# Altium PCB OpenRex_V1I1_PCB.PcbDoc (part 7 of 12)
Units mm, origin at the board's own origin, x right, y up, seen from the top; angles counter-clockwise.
Board outline 70 x 95 mm, 10 copper layers (L1, L2, L3, L4 (PWR), L5 (PWR), L6 (PWR), L7 (PWR), L8, L9, L10), stack 1.632 mm thick; 1080 components, 708 nets, 3831 pads, 2373 vias.
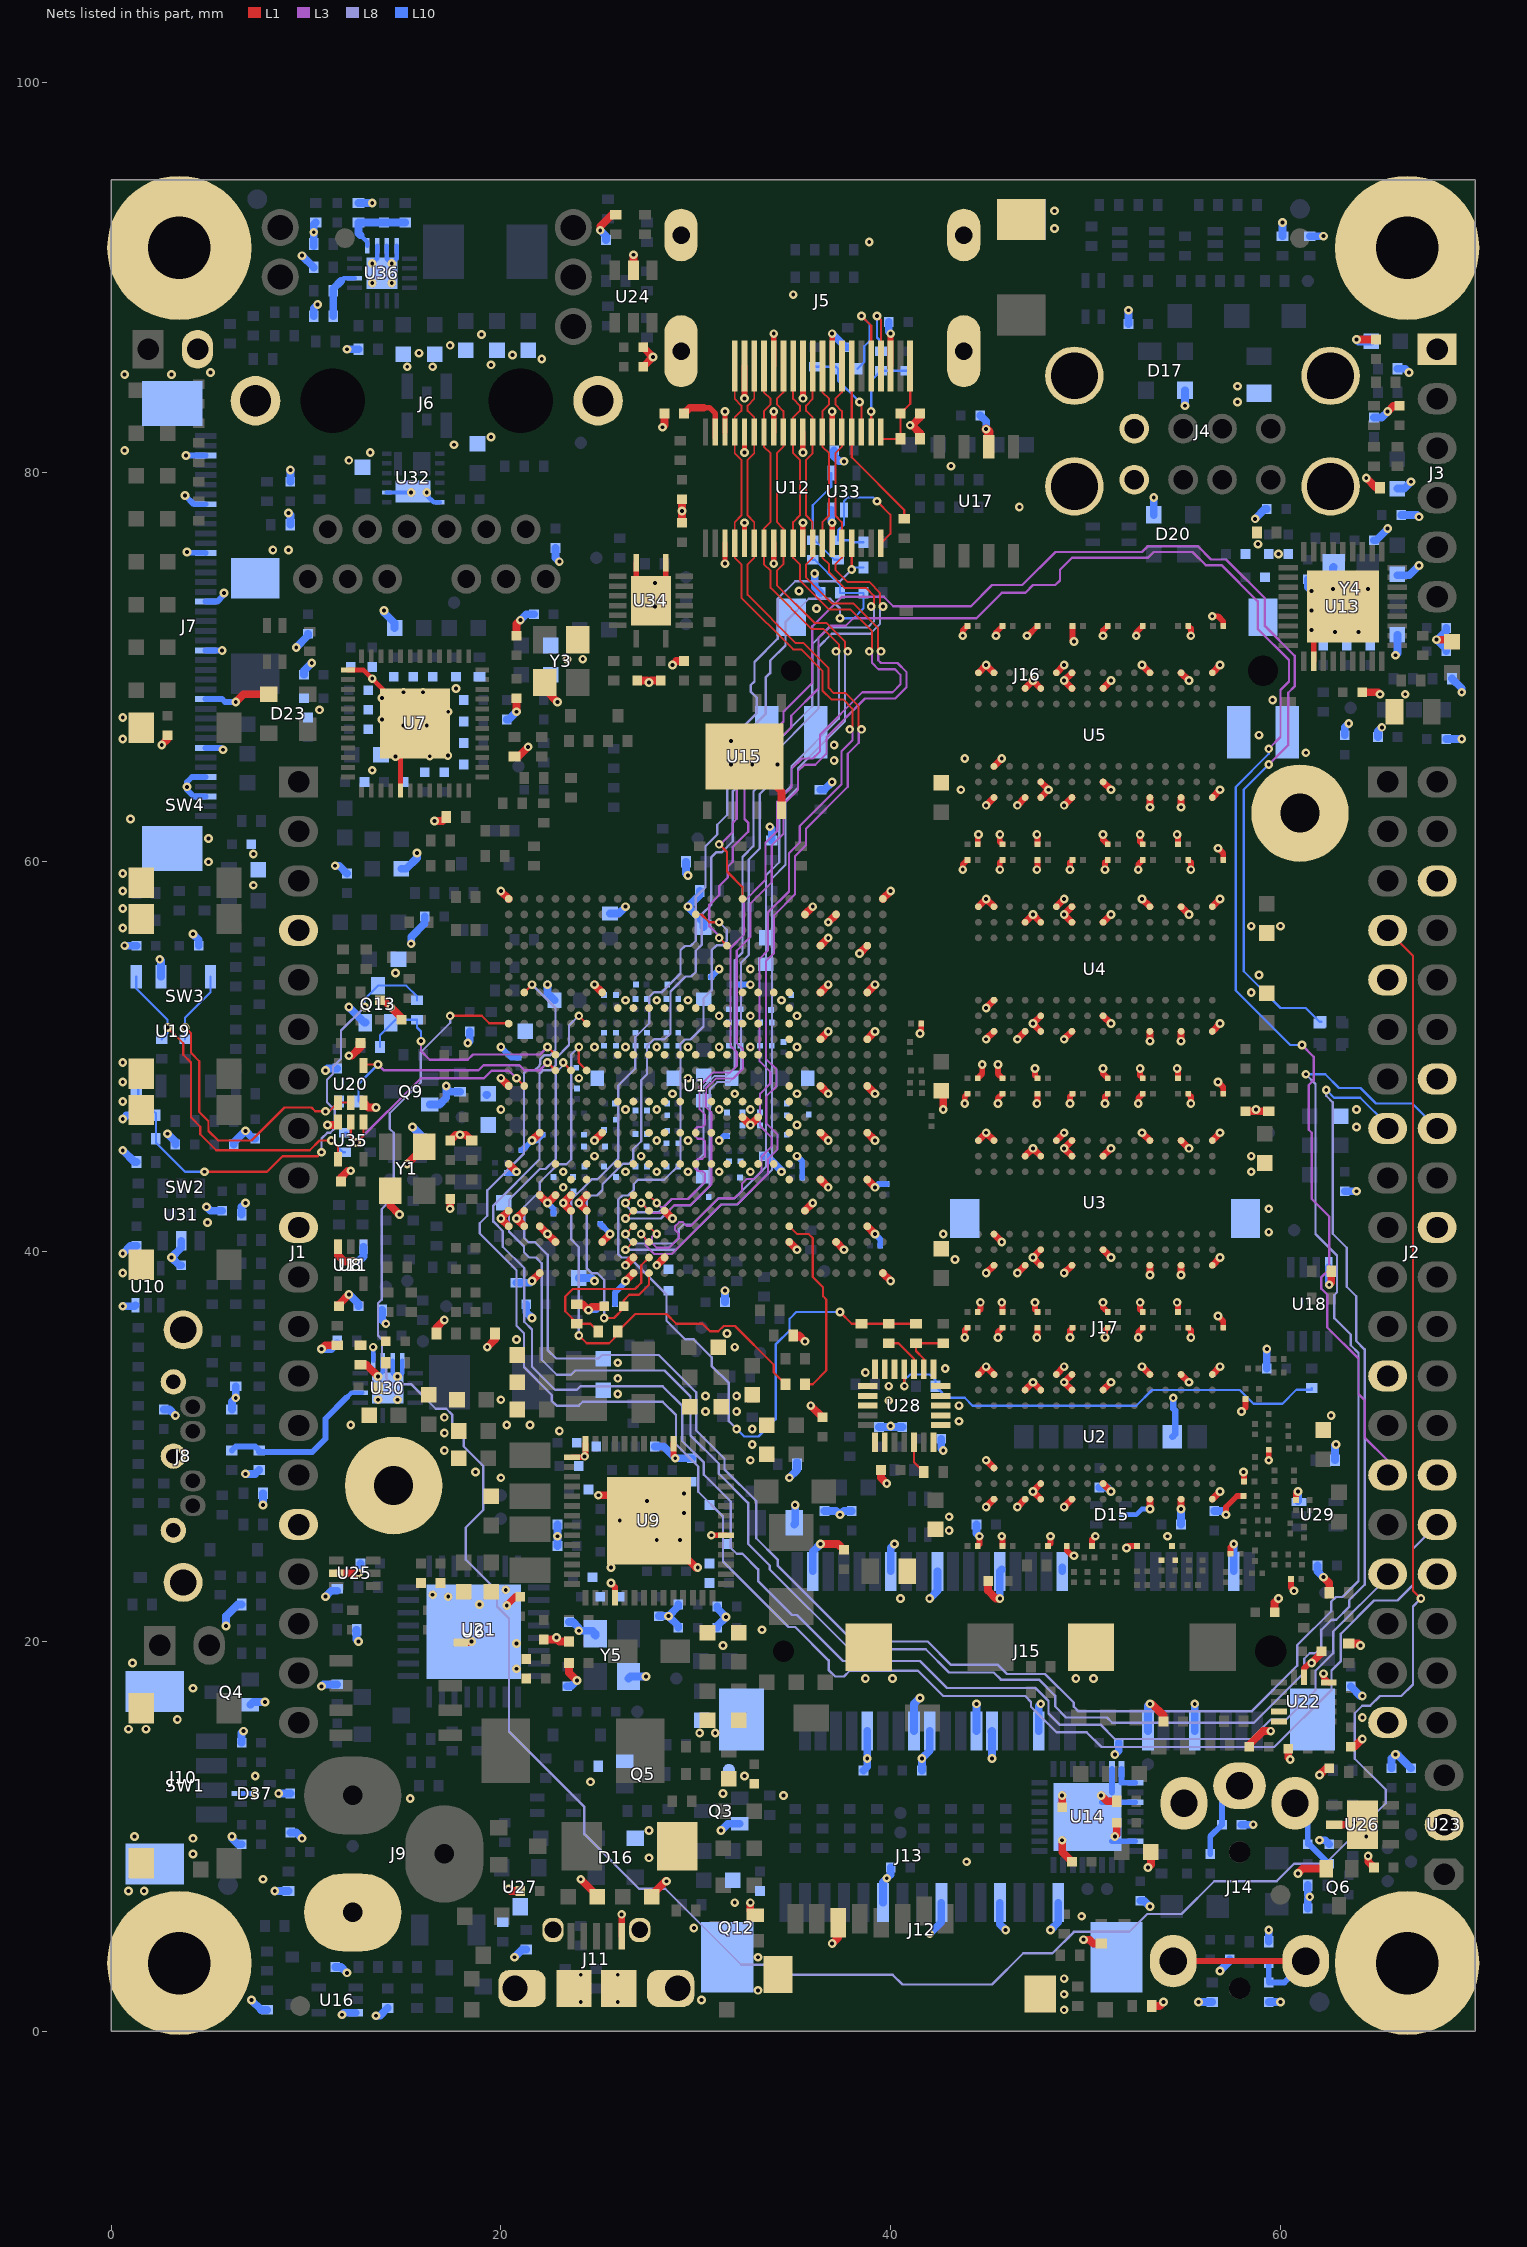
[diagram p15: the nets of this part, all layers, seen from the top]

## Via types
v1: diameter 0.45, hole 0.2, L1 to L10, tented both sides, 2369 vias
v2: diameter 1, hole 0.5, L1 to L10, tented top, 4 vias

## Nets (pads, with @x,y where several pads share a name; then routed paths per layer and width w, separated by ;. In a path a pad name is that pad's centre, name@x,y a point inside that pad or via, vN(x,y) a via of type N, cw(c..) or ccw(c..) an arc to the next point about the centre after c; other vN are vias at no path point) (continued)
FB_1V375: C410.1 R336.1 R339.2 U30.9 | length 0.7
  L10 w0.23: U30.9@13.45,34.4 U30.9@13.45,34.41 v1(13.45,35.1)
FB_3V3_HDR: C432.1 R399.1 R402.2 U36.9 | length 3.8
  L10 w0.23: 12.8,92.15 13.15,91.8 U36.9@13.15,91.61
  L10 w0.4: 12.8,92.15 12.7,92.25 R402.2@12.7,92.8 C432.1@14,92.8 R399.1@15.1,92.8
FIL_HP_OUTL: C287.1 FB22.2 J14.3 J14.4 | length 10.3
  L1 w0.3: J14.3@54.5,3.6 J14.4@61.3,3.6
  L10 w0.3: FB22.2@59.4,3.6 FB22.2@59.4,3.5 C287.1@59.4,2.5 60.2,2.5 J14.4@61.3,3.6
FIL_HP_OUTR: C286.1 FB21.2 J14.2 | length 3.9
  L10 w0.3: J14.2@60.75,11.7 61.4,11.05 FB21.2@61.4,9.6 61.479,9.6 62.479,8.6 C286.1@62.5,8.6
FIL_MIC_IN: C295.1 FB18.2 J14.1 | length 4.1
  L10 w0.3: FB18.2@56.4,9.1 56.4,10 C295.1@57,10.6 57,11.7 J14.1@57.9,12.6
FLEXCAN1_RX: R412.1 U1.D14 U20.4 | length 12.8
  L1 w0.114: U20.4@12.95,49.55 13,49.6 v1(13.7,49.6) ; v1(22.4,49.7) U1.D14@22.8,49.3
  L3 w0.12: v1(13.7,49.6) 14,49.3 18.845,49.3 19.11,49.565 20.95,49.565 21.2,49.315 22.015,49.315 v1(22.4,49.7)
  L10 w0.114: R412.1@12.7,47.7 12.7,48.6 v1(13.7,49.6)
FLEXCAN1_RX_BUFF: R117.1 R412.2 U19.4 U20.1 U20.2 | length 18.9
  L1 w0.114: v1(3.8,51.5) 4.1,51.2 4.1,50.2 4.53,49.77 4.53,47.17 5.004,46.696 5.004,46.196 5.496,45.704 7.204,45.704 8.9,47.4 10.28,47.4 10.48,47.2 v1(11,47.2) 11.2,47.2 U20.1@11.65,47.65 U20.2@12.3,47.65
  L10 w0.114: R117.1@3.8,50.9 v1(3.8,51.5) 3.8,52 5.105,53.305 U19.4@5.105,54.1 ; v1(11,47.2) 11.2,47.2 R412.2@11.7,47.7
FLEXCAN1_STBY: Q13.1 R280.1 R413.1 U1.D15 | length 12
  L1 w0.114: v1(22.4,50.5) U1.D15@22.8,50.1
  L3 w0.12: v1(15.9,50.8) 15.9,50.3 16.355,49.845 18.3,49.845 18.57,50.115 22.015,50.115 v1(22.4,50.5)
  L10 w0.114: R280.1@13.8,50.5 13.8,51.1 14.6,51.9 R413.1@15.7,51.9 15.7,51.5 15.9,51.3 v1(15.9,50.8)
FLEXCAN1_STBY_Q: Q13.3 R250.2 R382.1 R413.2 U19.8 | length 25.4
  L1 w0.114: v1(4.8,44.1) 8,44.1 8.8,44.9 10.6,44.9 v1(10.8,45.1)
  L8 w0.12: v1(10.8,45.1) 10.8,45.8 11.1,46.1 11.244,46.1 11.485,46.341 11.485,47.259 11.078,47.667 11.078,48.822 11.385,49.129 11.385,49.485 11.8,49.9 11.8,51.344 13,52.544 v1(13,52.55)
  L10 w0.114: U19.8@1.395,48.5 1.395,48.005 2.3,47.1 R382.1@2.3,45.8 2.3,45.6 3.8,44.1 v1(4.8,44.1) ; v1(13,52.55) 13,52.95 Q13.3@13.7,53.65 15.15,53.65 15.7,53.1 R413.2@15.7,52.9
FLEXCAN1_TX: R411.1 U1.B13 U35.1 U35.2 | length 13.6
  L1 w0.114: U35.2@12.3,46.65 12.3,45.9 v1(12.6,45.6) 12.95,45.95 U35.1@12.95,46.65 ; v1(20.8,48.9) U1.B13@21.2,48.5
  L3 w0.12: v1(12.6,45.6) 15.9,48.9 19.135,48.9 19.52,49.285 20.415,49.285 v1(20.8,48.9)
  L10 w0.114: R411.1@12,46.1 12.1,46.1 v1(12.6,45.6)
FLEXCAN1_TX_BUFF: R41.1 R411.2 U19.1 U35.4 | length 19.5
  L1 w0.114: v1(2.9,51.5) 3.7,50.7 3.7,50.1 4.1,49.7 4.1,46.896 4.58,46.416 4.58,46.02 5.4,45.2 10.2,45.2 10.7,45.7 v1(11.3,45.7) 11.65,45.35 U35.4@11.65,44.75
  L10 w0.114: U19.1@1.295,54.1 1.295,53.505 2.9,51.9 v1(2.9,51.5) 2.9,51.2 R41.1@2.6,50.9 ; v1(11.3,45.7) 11.9,45.1 R411.2@12,45.1
FLEXCAN2_RX: J2.16 U1.F14 | length 110.1
  L1 w0.114: v1(24,50.5) 24,49.7 U1.F14@24.4,49.3
  L8 w0.12: v1(24,50.5) 23.615,50.115 23.615,44.741 23.359,44.485 22.925,44.485 22,43.56 22,43.1 21.2,42.3 21.2,40.7 21.415,40.485 21.759,40.485 22.4,39.844 22.4,34.956 22.841,34.515 25.015,34.515 25.2,34.7 28.1,34.7 30.018,32.782 30.018,30.838 31.475,29.38 31.475,28.825 33.1,27.2 33.1,25.3 34.2,24.2 34.2,23.9 38.1,20 41.9,20 43.1,18.8 45.5,18.8 45.965,18.335 47.921,18.335 49.4,16.856 49.4,16.656 49.641,16.415 58.515,16.415 60.86,18.76 60.86,19.816 62.6,21.556 62.6,22.044 62.841,22.285 63.185,22.285 64,23.1 64,34.8 63.6,35.2 63.6,35.744 62.754,36.591 62.754,37.769 62.9,37.915 62.9,39.8 61.8,40.9 61.8,48.6 v1(61.3,49.1)
  L10 w0.114: v1(61.3,49.1) 62.3,49.1 63,48.4 64.1,48.4 64.9,47.6 66.76,47.6 J2.16@68.04,46.32
FLEXCAN2_TX: J2.15 U1.E14 | length 105.6
  L1 w0.114: v1(23.2,49.7) U1.E14@23.6,49.3
  L8 w0.12: v1(23.2,49.7) 23.2,49.56 22.815,49.175 22.815,44.771 22.289,44.244 22,44.244 20.415,42.659 20.415,41.029 21.185,40.259 21.185,39.971 21.456,39.7 21.8,39.7 22.1,39.4 22.1,34.456 22.871,33.685 23.6,33.685 23.815,33.9 28.4,33.9 29.728,32.572 29.728,30.572 31.185,29.115 31.185,28.609 32.685,27.109 32.685,25.015 33.8,23.9 33.8,23.7 37.9,19.6 41.8,19.6 42.99,18.41 45.29,18.41 45.655,18.045 47.605,18.045 48.44,17.21 48.44,16.66 49,16.1 51.1,16.1 51.365,15.835 58.635,15.835 61.215,18.415 61.215,19.115 61.5,19.4 61.8,19.4 62.1,19.7 62.1,20.6 62.615,21.115 62.859,21.115 63.52,21.776 63.52,22.12 64.315,22.915 64.315,34.985 63.885,35.415 63.885,37.715 63.4,38.2 63.4,40.2 62.685,40.915 62.685,47.659 62.35,47.994 v1(62.35,48.3)
  L10 w0.114: v1(62.35,48.3) 62.75,47.9 64.094,47.9 65.5,46.494 J2.15@65.5,46.32
FS_1V375: R334.1 R337.2 U30.6 | length 8.8
  L10 w0.23: 12.1,32.528 12.322,32.75 U30.6@12.79,32.75 U30.6@12.9,32.75
  L10 w0.3: R334.1@6.2,29.8 6.4,30 7.4,30 R337.2@7.6,29.8 7.6,29.725 10.325,29.725 11,30.4 11,31.428 12.1,32.528
FS_3V3_HDR: R397.1 R400.2 U36.6 | length 2.8
  L10 w0.23: 11.8,89.8 11.95,89.95 U36.6@12.49,89.95 U36.6@12.5,89.95
  L10 w0.4: R400.2@11.4,88 R397.1@11.4,89.4 ; R397.1@11.4,89.3 R397.1@11.4,89.4 ; 11.8,89.8 R397.1@11.4,89.4
GND: C1.2 C2.2 C3.2 C4.2 C5.2 C6.2 C7.2 C8.2 C9.2 C10.2 C11.2 C12.2 C19.2 C21.2 C22.2 C23.2 C24.2 C25.2 C26.2 C27.2 C28.2 C29.2 C30.2 C31.2 C32.2 C33.2 C34.2 C35.2 C36.2 C37.2 C38.2 C39.2 C40.2 C41.2 C42.2 C43.2 C44.2 C45.2 C46.2 C47.2 C48.2 C49.2 C50.2 C51.2 C52.2 C53.2 C54.2 C55.2 C56.2 C57.2 C58.2 C59.2 C60.2 C61.2 C62.2 C64.2 C68.2 C73.2 C75.2 C76.2 C77.2 C78.2 C79.2 C80.2 C81.2 C82.2 C83.2 C84.2 C87.2 C88.2 C89.2 C90.2 C91.2 C92.2 C93.2 C94.2 C95.2 C96.2 C97.2 C98.2 C99.2 C100.2 C101.2 C102.2 C103.2 C104.2 C105.2 C106.2 C107.2 C108.2 C109.2 C110.2 C111.2 C112.2 C113.2 C114.2 C115.2 C116.2 C117.2 C118.2 C119.2 C120.2 C121.2 C122.2 C123.2 C124.2 C125.2 C126.2 C127.2 C128.2 C129.2 C130.2 C131.2 C132.2 C133.2 C134.2 C135.2 C136.2 C137.2 C138.2 C139.2 C140.2 C141.2 C142.2 C143.2 C144.2 C145.2 C146.2 C147.2 C148.2 C149.2 C150.2 C151.2 C152.2 C153.2 C154.2 C155.2 C156.2 C157.2 C158.2 C159.2 C160.2 C161.2 C162.2 C163.2 C164.2 C165.2 C166.2 C167.2 C168.2 C169.2 C170.2 C171.2 C172.2 C173.2 C174.2 C175.2 C176.2 C177.2 C178.2 C179.2 C180.2 C181.2 C182.2 C183.2 C184.2 C185.2 C186.2 C187.2 C188.2 C189.2 C190.2 C191.2 C192.2 C193.2 C194.2 C195.2 C196.2 C197.2 C198.2 C199.2 C200.2 C201.2 C202.2 C203.2 C204.2 C205.2 C207.2 C208.2 C209.2 C210.2 C211.2 C212.2 C213.2 C214.2 C215.2 C216.2 C217.2 C218.2 C219.2 C220.2 C221.2 C222.2 C223.1 C224.1 C225.2 C226.2 C227.2 C228.2 C229.2 C230.1 C231.2 C232.2 C233.2 C234.2 C235.2 C236.2 C237.2 C238.2 C239.2 C240.2 C242.2 C243.2 C244.2 C245.1 C246.2 C247.2 C248.2 C249.2 C250.2 C251.1 C252.2 C253.2 C254.2 C255.2 C256.2 C257.2 C258.2 C259.2 C260.2 C261.2 C262.2 C263.2 C264.2 C265.2 C266.2 C267.2 C268.2 C269.2 C270.2 C271.1 C272.1 C273.2 C274.1 C275.1 C276.1 C277.2 C278.2 C279.2 C280.2 C281.2 C282.2 C283.2 C286.2 C287.2 C288.2 C289.2 C292.2 C293.2 C295.2 C296.2 C297.2 C298.1 C299.2 C300.2 C301.2 C302.2 C303.2 C304.2 C305.2 C306.2 C307.2 C308.2 C309.1 C310.2 C311.2 C312.2 C313.2 C314.2 C315.2 C316.2 C317.2 C318.2 C319.2 C320.2 C321.2 C324.1 C325.2 C326.1 C329.2 C330.2 C331.2 C332.2 C333.2 C334.2 C335.2 C336.2 C337.2 C338.2 C339.2 C341.2 C342.2 C343.2 C344.2 C345.2 C346.2 C347.2 C348.2 C349.2 C350.2 C351.2 C352.2 C353.2 C354.2 C355.2 C356.2 C357.2 C358.2 C359.2 C360.2 C361.2 C362.2 C363.2 C364.2 C365.2 C366.2 C367.2 C368.2 C369.2 C370.2 C371.2 C372.2 C373.2 C374.2 C375.2 C376.2 C377.2 C378.2 C379.2 C380.2 C381.2 C382.2 C383.2 C384.2 C385.2 C386.2 C387.2 C388.2 C389.2 C391.2 C393.2 C394.2 C395.2 C396.2 C397.2 C398.2 C399.2 C400.2 C401.2 C402.2 C403.2 C404.2 C405.2 C406.2 C407.2 C408.2 C409.2 C412.2 C413.2 C414.2 C415.2 C416.2 C417.2 C418.2 C419.2 C420.2 C421.2 C422.2 C423.2 C424.2 C425.2 C426.2 C427.2 C428.2 C429.2 C430.2 C431.2 C434.2 C435.2 C436.2 C437.2 D4.2 D8.2 D12.1 D15.2 D16.3 D17.3 D19.2 D20.3 D23.3 D31.2 D32.2 D37.2 J1.4 J1.10 J1.16 J2.6 J2.9 J2.14 J2.20 J2.25 J2.30 J2.34 J2.39 J3.1 J4.4 J4.8 J4.9 J4.10 J4.11 J4.12 J5.2 J5.5 J5.8 J5.11 J5.17 J5.MTG1 J5.MTG2 J5.MTG3 J5.MTG4 J6.18 J6.19 J7.3 J7.5 J7.8 J7.13 J7.18 J7.23 J7.28 J7.33 J7.38 J7.41 J7.42 J8.1 J8.4 J8.7 J8.8 J8.9 J9.2 J10.5 J10.6 J11.5 J11.6 J11.7 J11.8 J11.9 J11.10 J11.11 J12.1 J12.4 J12.7 J12.10 J12.16 J12.17 J13.6 J13.11 J13.12 J14.6 J15.4 J15.9 J15.15 J15.18 J15.21 J15.26 J15.27 J15.29 J15.34 J15.35 J15.37 J15.40 J15.43 J15.50 J15.53 J15.54 J16.1 J16.2 J16.3 J16.4 J16.5 J16.6 J17.C5 J17.G1 J17.G2 JP2.2 MH1.1 MH2.1 MH3.1 MH4.1 MH5.1 MH6.1 Q3.2 Q4.2 Q5.2 Q6.2 Q9.2 Q12.2 Q13.2 R4.1 R5.1 R6.1 R7.1 R8.1 R9.1 R10.2 R16.1 R17.1 R20.2 R26.1 R30.1 R32.1 R37.1 R47.1 R54.1 R56.1 R58.1 R61.1 R84.2 R99.1 R101.1 R102.1 R115.2 R139.1 R144.1 R157.1 R160.1 R163.1 R164.1 R166.1 R174.1 R175.1 R182.2 R191.1 R199.1 R205.1 R210.1 R211.1 R216.2 R220.1 R221.1 R222.2 R223.1 R224.1 R230.1 R231.1 R232.1 R233.1 R234.2 R237.1 R239.1 R250.1 R259.1 R265.1 R274.1 R296.1 R301.1 R303.1 R305.1 R306.1 R307.1 R308.1 R309.1 R310.1 R311.2 R316.2 R337.1 R338.1 R339.1 R342.1 R343.1 R344.1 R346.1 R393.1 R394.1 R395.1 R396.1 R400.1 R401.1 R402.1 R406.1 R407.1 R408.1 SW1.3 SW1.4 SW2.3 SW2.4 SW3.3 SW3.4 SW4.3 SW4.4 TP10.1 U1.A4 U1.A5 U1.A8 U1.A13 U1.A25 U1.AA7 U1.AA10 U1.AA13 U1.AA16 U1.AA19 U1.AA22 U1.AB3 U1.AB24 U1.AD4 U1.AD7 U1.AD10 U1.AD13 U1.AD16 U1.AD19 U1.AD22 U1.AE1 U1.AE25 U1.B4 U1.B5 U1.C1 U1.C4 U1.C6 U1.C10 U1.D3 U1.D6 U1.D8 U1.E5 U1.E6 U1.E7 U1.F5 U1.F6 U1.F7 U1.F8 U1.G3 U1.G10 U1.G19 U1.H8 U1.H12 U1.H15 U1.H18 U1.J2 U1.J8 U1.J12 U1.J15 U1.J18 U1.K8 U1.K10 U1.K12 U1.K15 U1.K18 U1.L2 U1.L5 U1.L8 U1.L10 U1.L12 U1.L15 U1.L18 U1.M8 U1.M10 U1.M12 U1.M15 U1.M18 U1.N8 U1.N10 U1.N15 U1.N18 U1.P8 U1.P10 U1.P12 U1.P15 U1.P18 U1.R8 U1.R12 U1.R15 U1.R17 U1.T8 U1.T11 U1.T12 U1.T15 U1.T17 U1.T19 U1.U8 U1.U11 U1.U12 U1.U15 U1.U17 U1.U19 U1.V8 U1.V19 U1.W3 U1.W7 U1.W8 U1.W9 U1.W10 U1.W11 U1.W12 U1.W13 U1.W15 U1.W16 U1.W17 U1.W18 U1.W19 U1.Y5 U1.Y24 U2.A9 U2.B1 U2.B3 U2.B9 U2.D1 U2.D8 U2.E1 U2.E2 U2.E8 U2.F9 U2.G1 U2.G8 U2.G9 U2.J2 U2.J8 U2.M1 U2.M9 U2.P1 U2.P9 U2.T1 U2.T9 U3.A9 U3.B1 U3.B3 U3.B9 U3.D1 U3.D8 U3.E1 U3.E2 U3.E8 U3.F9 U3.G1 U3.G8 U3.G9 U3.J2 U3.J8 U3.M1 U3.M9 U3.P1 U3.P9 U3.T1 U3.T9 U4.A9 U4.B1 U4.B3 U4.B9 U4.D1 U4.D8 U4.E1 U4.E2 U4.E8 U4.F9 U4.G1 U4.G8 U4.G9 U4.J2 U4.J8 U4.M1 U4.M9 U4.P1 U4.P9 U4.T1 U4.T9 U5.A9 U5.B1 U5.B3 U5.B9 U5.D1 U5.D8 U5.E1 U5.E2 U5.E8 U5.F9 U5.G1 U5.G8 U5.G9 U5.J2 U5.J8 U5.M1 U5.M9 U5.P1 U5.P9 U5.T1 U5.T9 U6.33 U7.13 U7.29 U7.49 U8.3 U9.5 U9.14 U9.15 U9.32 U9.48 U9.57 U10.3 U11.3 U12.3 U12.5 U12.8 U12.11 U12.14 U12.25 U12.28 U12.31 U12.34 U12.36 U13.11 U13.37 U14.1 U14.3 U14.7 U14.31 U14.32 U14.33 U15.4 U15.9 U16.3 U17.6 U18.4 U19.2 U20.3 U21.3 U22.5 U22.7 U22.12 U22.13 U23.2 U24.2 U25.2 U26.2 U26.7 U27.3 U28.1 U28.5 U28.6 U28.7 U28.8 U28.9 U28.10 U28.13 U28.14 U28.19 U28.20 U28.21 U28.22 U28.23 U28.24 U29.3 U30.10 U30.11 U30.12 U30.17 U31.2 U32.2 U32.12 U32.13 U33.3 U34.8 U34.9 U34.17 U35.3 U36.10 U36.11 U36.12 U36.17 Y1.2 Y1.4 Y3.2 Y3.4 Y4.2 Y4.4 Y5.2 Y5.4 | length 422
  L1 w0.25: U7.13@12.16,69.85 12.95,69.85 v1(13.4,69.4) 15.6,67.2 U7.49@15.6,67.1 14.85,66.35 U7.29@14.85,63.66
  L1 w0.28: U34.17@26.95,74.15 U34.9@26.95,75.35 ; U34.17@28.45,74.15 U34.8@28.45,75.35 ; v1(31.5,75.3) U12.3@31.5,76.35 ; U12.36@31.5,82.05 v1(31.5,83.1) ; U12.5@32.5,76.05 v1(32.5,77.4) ; v1(32.5,81) U12.34@32.5,82.05 ; v1(34,75.3) U12.8@34,76.35 ; U12.31@34,82.05 v1(34,83.1) ; U12.11@35.5,76.05 v1(35.5,77.4) ; v1(35.5,81) U12.28@35.5,82.05 ; U12.14@37,76.05 U12.14@37,76.35 v1(37,77.4) ; U12.25@37,82.05 v1(37,83.1) ; U13.11@61.7,70.3 U13.37@61.7,71.6
  L1 w0.3: U9.15@23.65,29.45 24.25,29.45 24.35,29.55 U9.14@24.35,30.15 ; v1(25.65,23) 25.85,22.8 U9.32@25.85,22.25 ; U9.5@28.85,30.15 28.85,29.5 v1(28.95,29.4) ; v1(30.8,25.45) U9.48@31.55,25.45 ; v1(32.5,83.78) J5.2@32.5,85.44 ; J5.5@34,85.44 v1(34,87.1) ; v1(35.5,83.78) J5.8@35.5,85.44 ; J5.11@37,85.44 v1(37,87.1) ; J5.17@40,85.44 v1(40,87.1) ; v1(41.5,51.2) 41.565,51.265 R10.2@41.565,51.7 ; v1(43.7,59.6) 43.7,59.865 C49.2@43.935,60.1 ; v1(43.7,71.6) 43.7,71.865 C59.2@43.935,72.1 ; v1(43.8,35.6) 43.8,35.965 C23.2@43.935,36.1 ; v1(43.8,47.6) 43.8,47.965 C39.2@43.935,48.1 ; C1.2@44.465,24.9 44.55,24.985 v1(44.55,25.4) ; C34.2@44.465,36.9 44.6,37.035 v1(44.6,37.4) ; C44.2@44.465,48.9 44.7,49.135 v1(44.7,49.6) ; C54.2@44.465,60.9 44.465,61.365 v1(44.5,61.4) ; v1(45.4,71.6) 45.4,71.765 C60.2@45.735,72.1 ; v1(45.5,35.6) 45.5,35.865 C24.2@45.735,36.1 ; v1(45.5,47.6) 45.5,47.865 C40.2@45.735,48.1 C40.2@45.6,47.965 ; v1(45.5,49.6) 45.5,49.135 C45.2@45.735,48.9 ; v1(45.6,59.6) 45.6,59.965 C50.2@45.735,60.1 ; v1(45.6,61.4) 45.6,61.035 C55.2@45.735,60.9 ; v1(45.7,25.4) 45.735,25.365 C2.2@45.735,24.9 ; v1(45.7,37.4) 45.735,37.365 C35.2@45.735,36.9 ; v1(47,71.6) 47.035,71.6 C203.2@47.535,72.1 ; v1(47.4,37.4) 47.4,37.035 C5.2@47.535,36.9 ; v1(47.4,49.4) 47.4,49.035 C8.2@47.535,48.9 ; v1(47.5,35.6) 47.535,35.635 C25.2@47.535,36.1 ; v1(47.5,59.6) 47.535,59.635 C51.2@47.535,60.1 ; v1(47.5,61.4) 47.535,61.365 C10.2@47.535,60.9 ; v1@47.535,47.735 C41.2@47.535,48.1 ; C4.2@48.065,24.9 48.2,25.035 v1(48.2,25.4) ; C12.2@49.035,24.9 49.035,24.665 49.3,24.4 v1(49.4,24.4) ; v1(49.2,35.6) 49.2,35.965 R4.1@49.335,36.1 ; v1(49.2,47.6) 49.2,47.965 R5.1@49.335,48.1 ; v1(49.2,59.6) 49.2,59.965 R8.1@49.335,60.1 ; R9.1@49.335,72.1 49.335,71.365 v1(49.4,71.3) ; C319.2@50.335,24.9 50.335,25.235 v1(50.5,25.4) ; v1(50.9,37.4) 50.9,37.135 C36.2@51.135,36.9 C36.2@51,37.035 ; v1(50.9,49.4) 50.9,49.135 C46.2@51.135,48.9 C46.2@51,49.035 ; v1(50.9,61.4) 50.9,61.135 C56.2@51.135,60.9 ; v1(50.9,71.6) 50.9,71.865 R309.1@51.135,72.1 ; v1(51,35.6) 51,35.965 R306.1@51.135,36.1 ; v1(51,47.6) 51,47.965 R307.1@51.135,48.1 ; v1(51,59.6) 51,59.965 R308.1@51.135,60.1 ; v1(52.1,24.8) 52.2,24.9 C21.2@52.635,24.9 ; v1(52.6,71.6) 52.6,71.765 C11.2@52.935,72.1 ; v1(52.7,35.6) 52.7,35.865 C3.2@52.935,36.1 C3.2@52.8,35.965 ; v1(52.7,47.6) 52.7,47.865 C6.2@52.935,48.1 C6.2@52.8,47.965 ; v1(52.7,59.6) 52.7,59.865 C9.2@52.935,60.1 C9.2@52.8,59.965 ; v1(52.8,37.4) 52.8,37.035 C37.2@52.935,36.9 ; v1(52.8,49.4) 52.8,49.035 C47.2@52.935,48.9 ; v1(52.8,61.4) 52.8,61.035 C57.2@52.935,60.9 ; v1(54.7,37.4) 54.735,37.365 C38.2@54.735,36.9 ; v1(54.7,49.4) 54.735,49.365 C48.2@54.735,48.9 ; v1(54.7,61.4) 54.735,61.365 C58.2@54.735,60.9 ; C26.2@55.265,36.1 55.4,35.965 v1(55.4,35.6) ; C42.2@55.265,48.1 55.4,47.965 v1(55.4,47.6) ; C52.2@55.265,60.1 55.4,59.965 v1(55.4,59.6) ; C204.2@55.265,72.1 55.4,71.965 v1(55.4,71.6) ; v1(56.5,72.6) 56.8,72.6 57.065,72.335 C205.2@57.065,72.1 ; v1(56.8,36.7) 57.065,36.435 C30.2@57.065,36.1 ; v1(56.8,48.7) 57.065,48.435 C43.2@57.065,48.1 ; v1(56.8,60.7) 57.065,60.435 C53.2@57.065,60.1 ; v1(57.2,26.5) 57.2,26.9 57.765,27.465 C306.2@58.1,27.465 ; C317.2@57.435,24.5 57.435,24.835 v1(57.6,25) ; v1(58,31.8) 58.2,32 C229.2@58.2,32.435 ; v1(58.1,28.7) 58.135,28.665 C297.2@58.135,28.2 ; v1(59.4,29.3) C277.2@59.4,29.835 ; C308.2@60.535,23.2 60.535,22.765 v1(60.7,22.6) ; C305.2@60.8,27.265 60.8,27.6 v1(60.9,27.7) ; U22.7@61.2,18.175 61.2,18.6 v1@61.5,18.9 ; v1(62.2,18.35) 62.2,18.175 U22.5@62.475,17.9
  L1 w0.35: U21.3@17.95,19.95 18.45,19.95 v1(18.5,20) ; v1(20.3,21.85) 20.75,22.3 C385.2@21,22.3 ; J11.5@26.2,4.875 v1(26.2,6) ; U2.A9@44.5,33.7 v1(44.9,34.1) U2.B9@45.3,33.7 ; U3.A9@44.5,45.7 v1(44.9,46.1) U3.B9@45.3,45.7 ; U4.A9@44.5,57.7 v1(44.9,58.1) U4.B9@45.3,57.7 ; U5.A9@44.5,69.7 v1(44.9,70.1) U5.B9@45.3,69.7 ; v1(44.9,26.9) U2.B1@45.3,27.3 ; v1(44.9,29.3) U2.B3@45.3,28.9 ; v1(44.9,38.9) U3.B1@45.3,39.3 ; v1(44.9,50.9) U4.B1@45.3,51.3 ; v1(44.9,52.5) U4.B3@45.3,52.9 ; v1(44.9,62.9) U5.B1@45.3,63.3 ; U3.B3@45.3,40.9 v1(45.7,40.5) ; U5.B3@45.3,64.9 v1(45.7,65.3) ; v1(46.5,26.9) U2.D1@46.9,27.3 ; v1(46.5,38.9) U3.D1@46.9,39.3 ; v1(46.5,50.9) U4.D1@46.9,51.3 ; v1(46.5,62.9) U5.D1@46.9,63.3 ; U2.D8@46.9,32.9 v1(47.3,33.3) U2.E8@47.7,32.9 ; U3.D8@46.9,44.9 v1(47.3,45.3) U3.E8@47.7,44.9 ; U4.D8@46.9,56.9 v1(47.3,57.3) U4.E8@47.7,56.9 ; U5.D8@46.9,68.9 47.3,69.3 U5.E8@47.7,68.9 ; U2.E1@47.7,27.3 v1(47.3,27.7) U2.E2@47.7,28.1 ; U3.E1@47.7,39.3 v1(47.3,39.7) U3.E2@47.7,40.1 ; U4.E1@47.7,51.3 v1(47.3,51.7) U4.E2@47.7,52.1 ; U5.E1@47.7,63.3 v1(48.1,63.7) U5.E2@47.7,64.1 ; U2.F9@48.5,33.7 v1(48.9,34.1) ; U3.F9@48.5,45.7 v1(48.9,46.1) ; U4.F9@48.5,57.7 v1(48.9,58.1) ; U5.F9@48.5,69.7 v1(48.9,70.1) ; v1(48.9,26.9) U2.G1@49.3,27.3 ; v1(48.9,38.9) U3.G1@49.3,39.3 ; v1(48.9,50.9) U4.G1@49.3,51.3 ; v1(48.9,62.9) U5.G1@49.3,63.3 ; U2.G8@49.3,32.9 v1(48.9,33.3) U2.G9@49.3,33.7 ; U3.G8@49.3,44.9 v1(48.9,45.3) U3.G9@49.3,45.7 ; U4.G8@49.3,56.9 v1(48.9,57.3) U4.G9@49.3,57.7 ; U5.G8@49.3,68.9 v1(48.9,69.3) U5.G9@49.3,69.7 ; U2.J2@50.9,28.1 v1(51.3,27.7) ; U2.J8@50.9,32.9 v1(51.3,33.3) ; U3.J2@50.9,40.1 v1(51.3,39.7) ; U3.J8@50.9,44.9 v1(51.3,45.3) ; U4.J2@50.9,52.1 v1(51.3,51.7) ; U4.J8@50.9,56.9 v1(51.3,57.3) ; U5.J2@50.9,64.1 v1(51.3,63.7) ; U5.J8@50.9,68.9 v1(51.3,69.3) ; v1(52.9,34.1) U2.M9@53.3,33.7 ; v1(52.9,46.1) U3.M9@53.3,45.7 ; v1(52.9,58.1) U4.M9@53.3,57.7 ; v1(52.9,70.1) U5.M9@53.3,69.7 ; v1(53.3,26.8) U2.M1@53.3,27.3 ; v1(53.3,38.8) U3.M1@53.3,39.3 ; v1(53.3,50.8) U4.M1@53.3,51.3 ; v1(53.3,62.8) U5.M1@53.3,63.3 ; v1(54.9,26.8) U2.P1@54.9,27.3 ; U2.P9@54.9,33.7 v1(55.3,33.3) ; v1(54.9,38.8) U3.P1@54.9,39.3 ; U3.P9@54.9,45.7 v1(55.3,45.3) ; v1(54.9,50.8) U4.P1@54.9,51.3 ; U4.P9@54.9,57.7 v1(55.3,57.3) ; v1(54.9,62.8) U5.P1@54.9,63.3 ; U5.P9@54.9,69.7 v1(55.3,69.3) ; U2.T1@56.5,27.3 v1(56.9,27.7) ; U2.T9@56.5,33.7 v1(56.9,34.1) ; U3.T1@56.5,39.3 v1(56.9,39.7) ; U3.T9@56.5,45.7 v1(56.9,46.1) ; U4.T1@56.5,51.3 v1(56.9,51.7) ; U4.T9@56.5,57.7 v1(56.9,58.1) ; U5.T1@56.5,63.3 v1(56.9,63.7) ; U5.T9@56.5,69.7 v1(56.9,70.1)
  L1 w0.4: v1(2.6,66) 2.9,66.3 C307.2@2.9,66.5 ; v1(6.4,68.2) 6.8,68.6 D23.3@8.1,68.6 ; v1(10.8,35) 11,35.2 R144.1@11.6,35.2 ; v1(11.1,46.5) 11.5,46.5 U35.3@11.65,46.65 ; U25.2@11.55,23.5 v1@12.6,23.5 ; U11.3@11.65,40.25 11.65,39.8 11.95,39.5 v1(12.4,39.5) ; C386.2@11.7,37.2 11.7,37.306 v1@12.197,37.803 ; C423.2@11.8,43.6 11.8,43.8 12.15,44.15 v1(12.3,44.15) ; v1(12.2,50.05) 12.35,50.05 12.8,50.5 C310.2@12.8,50.7 ; R339.1@12.8,34.2 13.1,34.2 v1(13.7,33.6) ; U20.3@12.95,47.65 13.2,47.4 v1(13.6,47.4) ; C315.2@13.8,52.9 14,52.9 v1(14.35,52.55) 14.9,52 C316.2@14.9,51.9 ; Y1.4@14.325,43.125 14.325,42.375 v1(14.8,41.9) ; v1(15.2,44.5) Y1.2@16.075,45.375 ; v1(16.6,62.1) 17,62.1 R101.1@17.2,62.3 ; R17.1@16.7,35.8 16.7,36.1 v1(17.1,36.5) ; v1(17.4,42.2) C84.2@17.4,42.7 ; C83.2@17.4,45.7 17.7,46 v1(17.9,46) 18.2,46 R20.2@18.5,45.7 ; v1(19.3,35.1) 19.7,35.5 R16.1@19.7,35.8 ; v1(20,48.9) U1.A13@20.4,48.5 ; v1(20,58.5) U1.A25@20.4,58.1 ; v1(20.4,7.3) 20.5,7.2 C232.2@21,7.2 ; U1.A4@20.4,41.3 v1(20,41.7) U1.A5@20.4,42.1 ; U1.A8@20.4,44.5 v1(20.8,44.1) ; R30.1@20.7,65.4 20.9,65.4 v1(21.4,65.9) ; v1(20.8,67.7) C176.2@20.8,68.4 ; C175.2@20.8,71.6 20.8,72.2 v1(21,72.4) ; U1.B4@21.2,41.3 v1(20.8,41.7) U1.B5@21.2,42.1 ; v1(21.6,38.5) U1.C1@22,38.9 ; v1(21.6,45.7) U1.C10@22,46.1 ; U1.C4@22,41.3 v1(22.4,40.9) U1.D3@22.8,40.5 ; U1.C6@22,42.9 v1(22.4,42.5) U1.D6@22.8,42.9 ; C342.2@22.2,20.1 22.9,20.1 23,20 C437.2@23.5,20 ; Y3.4@22.25,69.2 22.25,68.85 v1(22.9,68.2) ; C339.2@23.5,18.9 23.5,18.4 v1(23.9,18) ; U1.E5@23.6,42.1 v1(23.2,42.5) U1.E6@23.6,42.9 ; R26.1@23.9,37.3 24.2,37.3 v1(24.5,37) 24.675,37.175 25.3,37.175 C207.2@25.3,37.2 ; v1(24.1,7.8) 24.95,6.95 C231.2@24.95,6.9 ; U1.F5@24.4,42.1 v1(24,42.5) U1.F6@24.4,42.9 ; v1(24.8,45.7) U1.G10@25.2,46.1 ; v1(24.8,53.7) U1.G19@25.2,53.3 ; v1(25,27.5) 26.3,27.5 U9.57@27.6,26.2 30,23.8 v1(30.1,23.8) ; v1(25.1,92.4) 25.1,92.6 25.7,93.2 R259.1@25.9,93.2 ; U1.G3@25.2,40.5 v1(25.6,40.9) ; v1(26.4,39.3) U1.J2@26.8,39.7 ; U24.2@26.8,90.45 v1(26.8,91.15) ; C418.2@27,69.3 27.5,69.3 v1(27.6,69.2) 27.7,69.3 C417.2@28.2,69.3 ; C326.1@27.3,85.4 v1(27.8,85.9) C396.2@27.3,86.4 ; D19.2@27.65,6.9 v1@28.475,7.725 ; v1(28,39.3) U1.L2@28.4,39.7 ; v1(28.3,82.3) 28.4,82.4 C215.2@28.4,83 ; U1.L5@28.4,42.1 v1(28.8,41.7) ; v1(28.8,70.1) 29,70.3 C384.2@29.4,70.3 ; C213.2@29.3,77.4 v1(29.3,78) C214.2@29.3,78.6 ; U1.T11@32.4,46.9 v1(32.8,46.5) U1.U11@33.2,46.9 ; U15.9@32.6,65.4 34.405,63.595 U15.4@34.405,62.65 U15.4@34.405,62.405 ; v1(32.8,6.6) 32.8,6.2 Q12.2@33.05,5.95 ; U1.W3@34.8,40.5 v1(35.2,40.1) ; R139.1@35,35.7 35.3,35.7 v1(35.6,35.4) ; U1.Y5@35.6,42.1 v1(36,42.5) ; U1.Y24@35.6,57.3 v1(36,57.7) ; v1(35.9,32.1) C404.2@36.5,31.5 ; v1(36.4,25) 37.3,25 C368.2@37.6,24.7 ; U1.AA7@36.4,43.7 v1(36.8,43.3) ; U1.AA10@36.4,46.1 v1(36.8,45.7) ; U1.AA13@36.4,48.5 v1(36.8,48.1) ; U1.AA16@36.4,50.9 v1(36.8,51.3) ; U1.AA19@36.4,53.3 v1(36.8,53.7) ; U1.AA22@36.4,55.7 v1(36.8,56.1) ; v1(36.8,56.9) U1.AB24@37.2,57.3 ; v1(37,4.5) 37.315,4.815 J13.6@37.315,5.575 ; U1.AB3@37.2,40.5 v1(37.6,40.1) ; v1(38.4,55.3) U1.AD22@38.8,55.7 ; U1.AD4@38.8,41.3 v1(39.2,40.9) ; U1.AD7@38.8,43.7 v1(39.2,43.3) ; U1.AD10@38.8,46.1 v1(39.2,45.7) ; U1.AD13@38.8,48.5 v1(39.2,48.1) ; U1.AD16@38.8,50.9 v1(39.2,51.3) ; U1.AD19@38.8,53.3 v1(39.2,53.7) ; C403.2@39.5,28.8 39.5,28.4 v1(39.8,28.1) ; U1.AE1@39.6,38.9 v1(40,38.5) ; U1.AE25@39.6,58.1 v1(40,58.5) ; v1(41,82.4) v1@41.1,82.4 ; R47.1@41.5,81.7 41.5,82 v1@41.1,82.4 ; C217.2@41.5,83 41.5,82.8 v1@41.1,82.4 ; C33.2@42.6,48.25 42.7,48.15 v1(42.7,47.3) ; C267.2@45,23.1 45,22.6 45.4,22.2 v1(45.6,22.2) ; v1(48.8,9.8) 48.8,9.2 C292.2@49.3,8.7 ; C281.2@48.8,11.5 v1(48.8,12.1) ; v1(49.9,4.7) 50.2,4.7 50.4,4.5 R54.1@50.8,4.5 ; v1(50.8,12.1) 51.1,11.8 R234.2@51.6,11.8 ; v1(51.5,10) 51.6,10.1 C283.2@51.6,10.7 ; v1(53.2,8.4) 53.35,8.55 C280.2@53.35,9.2 ; v1(53.3,16.8) 53.4,16.8 54,16.2 C264.2@54,15.9 ; R191.1@53.4,1.3 53.8,1.3 v1(54,1.5) ; C393.2@58.2,47.2 58.65,47.2 v1(58.75,47.3) 58.85,47.2 R274.1@59.4,47.2 ; C388.2@58.4,14.6 58.4,14.7 59.1,15.4 v1(59.5,15.4) ; C268.2@59.7,21.5 59.7,22 v1(59.9,22.2) ; C391.2@60.4,14.5 60.4,14.05 v1(60.5,13.95) ; v1(60.9,8.1) 61.15,8.35 Q6.2@62.35,8.35 ; v1(61.6,18.9) 62.1,19.4 C399.2@62.1,19.5 ; v1(62,13.15) 62.35,13.5 C389.2@62.5,13.5 ; v1(62.2,23.3) 62.5,23 R316.2@62.5,22.5 ; v1(62.5,38.3) 62.6,38.4 R115.2@62.6,39 ; U26.2@62.75,10.6 U26.7@64.2,10.6 ; R311.2@63.5,19.9 64,19.9 v1(64.1,19.8) ; C398.2@63.6,14.6 63.8,14.6 v1(64.2,15) ; v1(63.9,86.8) C416.2@64.9,86.8 ; C254.2@64.2,68.7 65,68.7 v1(65.1,68.6) ; v1(64.4,79.7) R216.2@64.9,79.2 ; v1(64.5,9) 64.5,8.7 C329.2@64.8,8.4 ; v1(65.5,83.1) 65.8,83.4 C237.2@66.1,83.4 ; v1(68,71.4) 68.7,71.4 D12.1@68.8,71.3
  L1 w0.5: v1(44.9,82.2) 45.035,82.065 U17.6@45.035,81.3
  L10 w0.23: v1(13.4,90.7) 13.65,90.95 U36.10@13.65,91.61 ; v1(13.7,33.6) 13.95,33.85 U30.10@13.95,34.41 ; U32.2@14.14,78.95 v1(15.4,78.95) ; U36.11@14.15,91.61 14.15,90.95 v1(14.4,90.7) 14.65,90.95 U36.12@14.65,91.6 ; U30.11@14.45,34.4 14.45,33.75 14.7,33.5 14.95,33.75 U30.12@14.95,34.4 ; v1(16.2,78.95) 16.2,78.8 16.55,78.45 U32.12@16.86,78.45
  L10 w0.25: D37.2@6.675,12.2 v1(7.4,12.2) ; D15.2@52.125,26.5 52.6,26.5 52.9,26.8 v1(53.3,26.8)
  L10 w0.3: v1(3.8,78.8) 4.25,78.35 J7.33@4.85,78.35 ; v1(3.85,80.85) J7.38@4.85,80.85 ; v1(3.9,75.9) 3.945,75.855 4.85,75.855 J7.28@4.85,75.85 ; J7.3@4.85,63.35 4.25,63.35 3.9,63.7 v1(3.9,63.85) 3.9,64.1 4.15,64.35 J7.5@4.85,64.35 ; J7.8@4.85,65.85 5.65,65.85 v1(5.75,65.75) ; J7.13@4.85,68.35 5.7,68.35 5.85,68.2 v1(6.4,68.2) ; J7.18@4.85,70.85 v1(5.7,70.85) ; J7.23@4.85,73.35 5.45,73.35 5.8,73.7 v1(5.8,73.8) ; v1(20,50.5) 20.535,49.965 R99.1@20.9,49.965 ; C211.2@20.3,44.035 20.735,44.035 v1(20.8,44.1) ; C212.2@21.065,45.2 21.1,45.2 v1(21.6,45.7) 21.835,45.7 R56.1@22.135,46 ; v1(22.4,42.5) 22.7,42.2 R160.1@22.7,41.965 ; v1(24.5,37) 24.9,37 25.2,37.3 R32.1@25.335,37.3 ; R61.1@25.1,41.435 25.6,40.935 v1(25.6,40.9) ; C144.2@30.765,54.1 30.8,54.1 v1(31.2,54.5) ; v1(31.2,45.7) 31.435,45.935 C105.2@31.6,45.935 ; C155.2@32.265,53.7 v1(32.8,53.7) ; v1(35.2,44.9) 35.465,44.635 C157.2@35.465,44.4 C79.2@35.465,43.8 ; v1(39.2,40.9) 39.465,40.635 C7.2@39.465,40.3 ; v1(39.2,43.3) 39.365,43.465 R7.1@39.8,43.465 ; U14.33@50.85,11.75 U14.3@52.55,11.75 ; U14.33@51.35,9.75 U14.7@52.55,9.75 ; U14.33@51.35,12.25 U14.31@51.35,13.45 ; U14.32@51.85,13.45 51.85,12.75 U14.1@52.55,12.75
  L10 w0.35: J17.C5@54.45,30.5 54.6,30.65 54.6,31.857 54.5,31.957 v1(54.5,32.5)
  L10 w0.4: v1(0.6,37.2) 1.2,37.2 U10.3@1.25,37.25 ; v1(0.6,39.9) 1,40.3 C413.2@1.3,40.3 ; v1(0.6,45.2) 1.2,44.6 R303.1@1.3,44.6 ; v1(0.6,46.8) 0.8,47 R250.1@1.3,47 ; v1(0.7,55.7) C397.2@1.3,55.7 ; v1(2.5,55) 2.565,54.935 U19.2@2.565,54.1 ; C382.2@2.7,31.9 3,31.9 v1(3.3,31.6) ; v1(2.9,46.05) 3.3,45.65 C311.2@3.3,45.5 ; C87.2@3.6,39.3 3.5,39.3 v1(3.1,39.7) 3.6,40.2 U31.2@3.6,40.55 ; v1(4.2,56.3) 4.5,56 C309.1@4.5,55.7 ; v1(4.9,42.3) 5.1,42.1 C412.2@5.7,42.1 ; v1(5.9,20.8) 5.9,21.3 6.5,21.9 R239.1@6.7,21.9 ; v1(6.2,10) 6.2,9.9 6.5,9.6 C178.2@6.7,9.6 ; R205.1@6.2,31.9 6.2,32.3 v1(6.4,32.5) R211.1@6.4,33.1 ; C312.2@6.3,45.5 6.3,45.6 v1(6.9,46.2) 7.3,45.8 C313.2@7.4,45.8 ; C179.2@6.7,14.8 6.7,15.3 v1(6.8,15.4) ; R210.1@6.7,41.9 6.7,42.3 v1(6.9,42.5) ; v1(6.9,28.6) 7.4,28.6 R337.1@7.6,28.8 ; Q4.2@7.15,16.75 7.3,16.9 v1(7.9,16.9) ; v1(7.2,1.6) 7.7,1.1 R174.1@8,1.1 ; v1(7.8,27) R338.1@7.8,27.6 ; v1(8.4,7.2) R393.1@9.1,7.2 ; v1(8.6,12.2) C210.2@9.2,12.2 ; v1(9.1,77.9) 9.2,77.8 R102.1@9.2,77.3 ; C177.2@9.2,10.2 9.5,10.2 v1(9.8,9.9) ; C275.1@9.2,79.5 v1(9.2,80.1) ; v1(9.5,71) 10.1,71.6 C276.1@10.1,71.7 ; v1(9.8,91.1) R406.1@10.4,90.5 ; C181.2@9.9,69.6 9.9,69.8 v1(10.3,70.2) ; R400.1@10.4,88 10.4,88.4 v1(10.6,88.6) ; R407.1@10.4,91.6 v1(10.4,92.3) ; v1@10.4,92.2 10.4,92.7 R408.1@10.5,92.8 ; v1(10.8,17.7) 10.9,17.8 R396.1@11.6,17.8 ; v1(10.8,35) 11.3,35 R343.1@11.6,35.3 ; v1(11,22.3) 11.3,22.6 R395.1@11.6,22.6 ; v1(11,49.3) 11.1,49.4 C298.1@11.6,49.4 ; C230.1@11.5,3.3 11.8,3.3 v1(12.1,3) ; v1(11.5,59.8) 11.7,59.8 C314.2@12.1,59.4 ; v1(11.85,0.85) 11.95,0.95 U16.3@12.55,0.95 ; v1(12.1,86.3) R401.1@12.7,86.3 ; v1(12.2,52.55) 13,51.75 Q13.2@13.05,51.75 ; v1@12.22,37.8 12.7,37.32 C89.2@12.7,37.2 ; v1(12.4,39.5) 12.7,39.5 12.95,39.75 U8.3@12.95,40.25 ; R394.1@12.55,20.55 R394.1@12.6,20.6 12.6,20.1 v1(12.7,20) ; v1(12.7,23.5) 12.8,23.6 C395.2@12.8,24 ; R402.1@12.7,93.8 v1(13.4,93.8) ; v1(13.6,0.8) 13.8,0.8 R305.1@14.2,1.2 ; R344.1@13.9,37 13.9,36.5 v1(14.1,36.3) ; v1(14,72.9) 14,72.8 14.55,72.25 C186.2@14.55,72 ; C194.2@14.9,59.65 15.15,59.65 15.7,60.2 v1(15.7,60.45) ; v1(15.4,55.8) 15.4,56.142 16.1,56.842 C153.2@16.1,57.2 ; v1(15.47,46.4) 15.9,45.97 R58.1@15.9,45.8 ; Q9.2@16.35,47.55 16.85,47.55 17.2,47.9 v1@17.2,48.4 ; v1(17.2,48.5) v1@17.2,48.4 ; R175.1@17.9,48.2 17.4,48.2 v1@17.2,48.4 ; v1(18.3,50.7) 18.4,50.8 C209.2@18.4,51.3 ; C137.2@19.275,48.025 19.25,48.05 C137.2@19.3,48.05 ; C192.2@20.3,67.3 20.4,67.3 v1(20.8,67.7) ; v1(20.7,3.8) 21.1,4.2 R296.1@21.3,4.2 ; R37.1@20.8,38.4 21.5,38.4 v1(21.6,38.5) ; v1(21,72.4) 21.3,72.7 C272.1@21.7,72.7 ; C78.2@21.3,37.3 21.3,36.9 v1(21.6,36.6) ; v1(22.4,53.7) 22.4,53.25 C128.2@22.75,52.9 ; C274.1@22.8,76.1 22.8,75.6 v1(23,75.4) ; C372.2@22.9,24.9 v1(22.9,25.4) C373.2@22.9,26 ; R199.1@23.3,2.2 23.4,2.2 v1(24.1,1.5) ; C224.1@23.4,17.7 23.6,17.7 v1(23.9,18) ; C223.1@23.5,21 23.7,21 24,20.7 v1(24,20.55) 24.7,20.55 Y5.4@24.85,20.4 ; C141.2@24,38.65 24.65,38.65 v1(24.8,38.5) ; Y5.4@24.8,20.35 Y5.4@24.85,20.3 ; v1(25.1,92.4) 25.4,92.1 C273.2@25.4,91.9 ; C129.2@25.6,57.35 26.05,57.35 v1(26.4,57.7) ; Y5.2@26.55,18.1 26.65,18.2 v1(27.45,18.2) ; C344.2@27.9,30 28.35,30 v1(28.95,29.4) C380.2@29.8,29.4 ; C337.2@28.1,21.3 v1(28.6,21.3) ; C338.2@29.1,20.7 29.1,20.8 v1(28.6,21.3) ; C341.2@29.1,21.9 29.1,21.8 v1(28.6,21.3) ; R166.1@29.5,60 29.5,59.4 v1(29.6,59.3) ; R164.1@30.2,58.5 30.2,58.3 v1(29.6,57.7) 30.4,56.9 C147.2@30.4,56.65 ; C262.2@31.1,20.7 31.1,20.8 v1(31.55,21.25) 31.1,21.7 C343.2@31.1,21.8 ; v1(31.3,10.3) 31.65,10.65 Q3.2@32.25,10.65 ; C247.2@31.5,37.4 v1(31.5,38) ; C208.2@33.5,44.9 33.658,44.9 34.4,44.158 v1(34.4,44.1) ; v1(33.8,61.8) 33.9,61.7 R163.1@33.9,61.1 ; v1(34.8,28.4) 35.2,28.8 R265.1@35.2,29.1 R265.1@35.2,29.2 ; C376.2@35.05,26 35.1,26.05 v1(35.1,27) ; J15.50@36,23.6 36,24.6 v1(36.4,25) ; v1(36.1,74.8) 36.1,74.1 R157.1@36.4,73.8 ; R346.1@36.4,63.7 36.6,63.7 v1(37,64.1) ; C265.2@36.6,26.7 37.2,26.7 37.3,26.6 v1@37.4,26.6 ; U33.3@36.95,78.05 36.95,77.45 v1(37,77.4) ; v1(37,87.1) 37.7,86.4 R182.2@37.8,86.4 ; C414.2@37.1,81.1 37.1,80.8 37.35,80.55 v1(37.6,80.55) ; v1(37.4,26.5) 37.6,26.7 C261.2@38,26.7 ; C266.2@38.6,13.375 38.8,13.575 v1(38.8,14) J15.43@38.8,15.4 ; C400.2@39.4,31 39.95,31 v1(40,31.05) 40.05,31 C401.2@40.6,31 ; J12.10@39.6,6.6 39.6,7.65 v1(39.8,7.85) 40,8.05 C296.2@40,8.4 ; C216.2@39.9,87.7 39.9,87.2 v1(40,87.1) ; J15.40@40,23.6 40,24.8 v1(40.2,25) ; J15.37@41.2,15.4 41.2,16.8 v1(41.5,17.1) ; C263.2@41.6,13.375 v1(41.6,14) 42,14.4 J15.35@42,15.4 ; v1(42,5) 42.6,5.6 J12.7@42.6,6.6 ; v1(42,22.2) 42.4,22.6 J15.34@42.4,23.6 ; C402.2@42.6,30.4 42.6,29.9 v1(42.7,29.8) ; J15.29@44.4,15.4 v1(44.4,16.8) ; C260.2@44.4,26 44.4,25.55 v1(44.55,25.4) ; C252.2@44.6,82.9 44.9,82.6 v1(44.9,82.2) ; J15.27@45.175,15.375 J15.27@45.2,15.4 v1(45.2,14) ; J12.4@45.6,6.6 45.6,5.5 v1(45.9,5.2) ; v1@45.6,22.3 J15.26@45.6,23.6 J15.26@45.7,23.7 ; J15.21@47.6,15.4 47.6,16.7 v1(47.7,16.8) ; v1(48.2,5.2) 48.6,5.6 J12.1@48.6,6.6 ; J15.18@48.8,23.6 J15.18@48.8,23.8 ; C383.2@50.7,27.9 51.1,27.9 v1(51.3,27.7) ; v1(51.5,14.2) 51.7,14.4 C282.2@51.7,14.8 ; C235.2@52.2,87.6 v1(52.2,88.3) ; C293.2@52.8,6.7 53,6.7 v1(53.3,6.4) ; J15.15@53.2,15.4 53.2,16.7 v1(53.3,16.8) ; D20.3@53.5,77.8 v1(53.5,78.7) ; C218.2@54.9,26 v1(54.9,26.8) ; v1(55.1,83.4) D17.3@55.1,84.2 ; J15.9@55.6,15.4 v1(55.6,16.8) ; v1(55.8,1.5) R233.1@56.5,1.5 ; C259.2@56.6,26.7 57,26.7 v1(57.2,26.5) ; v1(56.9,3.1) 57.4,3.6 C289.2@57.4,3.7 ; J15.4@57.6,23.6 v1(57.6,25) ; C295.2@58,10.6 v1(58.6,10.6) ; v1(58.7,77.6) 59.2,78.1 C253.2@59.3,78.1 ; C324.1@59.3,34 v1(59.3,35) ; C287.2@59.4,1.5 v1(60,1.5) ; R231.1@59.4,4.6 v1(59.4,5.2) ; R220.1@60.1,92.1 v1(60.1,92.8) ; U29.3@60.9,27.2 v1(60.9,27.7) ; C288.2@61.4,6.3 61.4,6.8 v1(61.5,6.9) 61.4,7 R230.1@61.4,7.5 ; C415.2@61.4,74.5 61.4,74.1 v1(61.6,73.9) ; R221.1@61.5,92.1 v1(62.2,92.1) ; C405.2@61.9,23.9 61.9,23.6 v1(62.2,23.3) ; v1(62,9.8) 62.3,9.8 C286.2@62.5,9.6 ; U18.4@62.475,39.2 62.475,38.325 v1(62.5,38.3) ; v1(62.7,74) 62.7,75.1 Y4.4@62.725,75.125 ; R310.1@62.8,29.3 62.8,30.05 v1(62.85,30.1) ; C300.2@63.3,43.1 v1(63.9,43.1) ; C303.2@63.3,66.5 63.3,66.9 v1(63.5,67.1) ; R232.1@63.6,10 R232.1@63.7,10 v1(64.4,10) ; C387.2@63.6,17.7 64.1,17.2 v1(64.2,17.2) ; v1(63.9,86.8) 64,86.7 D32.2@64.65,86.7 ; Y4.2@64.475,72.875 64.5,72.9 v1(64.5,74) ; C242.2@64.8,76.5 64.906,76.5 65.5,77.094 v1(65.5,77.1) ; C422.2@64.8,82.8 65.2,82.8 v1(65.5,83.1) ; C301.2@65,66.4 65,66.7 v1(65.2,66.9) ; C394.2@65.7,13.5 65.7,14 v1(65.9,14.2) 66,14.2 66.05,14.15 C325.2@66.7,13.5 ; v1(65.9,70.6) 66,70.7 D31.2@66,71.65 ; D8.2@66,74.7 66.6,74.7 v1(67.1,75.2) ; D4.2@66,79.15 66.35,79.15 v1(66.7,79.5) ; R223.1@66,85.3 66.4,85.3 v1(66.6,85.1) ; C269.2@66.2,77.8 67,77.8 v1(67.1,77.7) ; C302.2@68.5,66.3 v1(69.3,66.3) ; C250.2@68.5,70.8 68.5,70.921 68.035,71.386 68.5,71.851 C251.1@68.5,72 ; R224.1@68.8,69.4 69.3,68.9 v1(69.3,68.7)
  other v1: 48.9,1.1 26,1.5 30.3,1.6 48.9,1.9 33.2,2.1 48.9,2.7 24.1,2.9 26,2.9 33.2,3.8 29.9,5.3 49.8,5.9 32,6.6 0.9,7.2 1.7,7.2 28.5,7.7 7.8,7.8 43.9,8.7 27.6,8.9 4.2,9.1 4.2,9.9 1.2,10 27.6,10.3 63.8,10.7 15.35,11.95 34.5,12.1 31.4,12.2 24.6,12.8 7.4,13.1 32.5,13.1 30.2,15.3 31,15.3 0.9,15.5 1.8,15.5 3.4,16 64.2,16.1 4.2,17.6 38.7,18.1 40.1,18.1 49.5,18.1 50.4,18.1 20.8,18.6 1.1,18.9 31.4,19.8 20.8,19.9 22.85,20.2 33.4,20.6 18.9,21.9 40.5,22.2 17.3,22.3 16.5,22.4 20.25,22.65 25.65,23.8 28,25.2 29.2,25.2 54.2,25.4 43,25.7 26.1,26.2 43,26.4 27.9,26.5 29.4,26.6 27.5,27.2 29.4,27.6 20,28.4 18.7,28.7 32.8,29.3 24.3,29.5 17.1,29.8 32.9,30.1 17.1,30.7 23,30.8 32.9,30.9 12.3,31.1 20.3,31.1 21.5,31.1 43.5,31.3 17.1,31.5 62.6,31.6 30.5,31.8 32.1,31.8 43.5,32.1 39.9,32.35 13.7,32.4 14.7,32.4 20,32.4 30.5,32.6 32.1,32.6 26,32.7 39.9,33.1 26,33.5 14.7,33.6 38.7,33.8 42.8,34 26,34.3 32,35.1 20.8,35.5 31.6,35.8 12.2,37.8 0.6,38.9 43.3,39.6 42.7,40.9 59.4,41 4.95,41.5 59.4,42.2 23.2,43.3 23.2,44.1 26.4,44.1 28,44.1 29.6,44.1 31.2,44.1 32.8,44.1 58.5,44.1 24.8,44.9 27.2,44.9 58.5,44.9 28,45.7 29.6,45.7 63.9,46.4 35.2,46.5 20,47.3 26.4,47.3 28,47.3 31.2,47.3 32.8,47.3 63.9,47.3 47.5,47.6 0.6,47.7 28.8,48.1 32,48.1 35.2,48.1 0.6,48.7 24,48.9 29.6,48.9 0.6,49.7 24.8,50.5 26.4,50.5 28,50.5 29.6,50.5 31.2,50.5 32.8,50.5 35.2,50.5 31.2,52.1 32.8,52.1 35.2,52.1 26.4,52.9 28,52.9 29.6,52.9 34.4,52.9 58.5,53.3 58.9,54.2 14.6,54.3 32.8,54.5 0.6,56.6 58.5,56.7 60,56.7 0.6,57.6 0.6,58.5 7.3,58.8 0.6,59.4 5,60 7.3,60.4 5,61.2 1,62.2 43.6,63.7 13.4,64.7 31.8,65 32.9,65 34.2,65 37.1,65.2 43.8,65.3 14.6,65.4 16.35,65.42 17.28,65.45 61.3,65.6 37.1,66 31.8,66.2 0.6,66.3 58.9,66.5 15,67 16.2,67 13.9,67.3 0.6,67.4 17.3,67.7 10.7,67.8 59.6,68.3 13.9,68.4 66.4,68.6 15,68.7 16,68.7 17.7,68.9 47.3,69.3 23.4,70.4 24.2,70.4 62.8,71.8 64,71.8 61.6,71.9 61.6,72.9 36.2,73 27.9,73.1 35.3,73.9 27.9,74.3 59.9,75.8 8.3,76 9.1,76 58.85,76.3 46.6,78.2 43.1,80.3 12.2,80.6 13.3,81 0.7,81.1 17.6,81.4 19.5,81.8 57.8,83.6 57.8,84.4 0.7,85 3.1,85 5.1,85.1 15.2,85.4 16.5,85.4 19.5,85.5 22.1,85.8 20.6,86 15.8,86.1 17.4,86.5 19,87.05 35,89.1 13.4,89.7 14.4,89.7 38.9,91.8 48.4,92.5 48.4,93.4
GPIO_OR_CLK: J2.7 U1.A17 | length 149.5
  L1 w0.114: v1(17.4,52.1) 19.015,52.1 19.4,51.715 20.385,51.715 U1.A17@20.4,51.7 ; J2.7@65.5,56.48 66.8,55.18 66.8,22.6 v1(67.2,22.2)
  L8 w0.12: v1(17.4,52.1) 17.4,51.744 15.885,50.229 15.885,48.685 14.3,47.1 14.3,46.3 14.5,46.1 14.5,42.8 13.885,42.185 13.885,37.541 13.7,37.356 13.7,35.7 13.9,35.5 13.9,34.4 14.125,34.175 14.125,33.5 14.435,33.19 15.41,33.19 16.656,31.944 17.2,31.944 17.5,31.644 17.5,31 18.1,30.4 18.1,30 19.1,29 19.1,26.744 18.2,25.844 18.2,24.2 19.8,22.6 19.8,21.8 20.415,21.185 20.415,15.385 24.285,11.515 24.285,10.115 27.085,7.315 28.429,7.315 32.329,3.415 33.581,3.415 34.096,2.9 40.1,2.9 40.6,2.4 45.2,2.4 46.8,4 48.3,4 49.4,5.1 52.244,5.1 53.159,6.015 54.915,6.015 56.6,7.7 59.8,7.7 60.7,8.6 62.3,8.6 65.4,11.7 65.4,12.4 63.815,13.985 63.815,16.315 64.2,16.7 64.6,16.7 65.1,17.2 66.2,17.2 66.8,17.8 66.8,21.8 v1(67.2,22.2)
GPIO_OR_PWM_1: J2.29 U1.R22 | length 95.1
  L1 w0.114: v1(31.2,56.1) U1.R22@31.6,55.7
  L3 w0.12: v1(31.2,56.1) 31.2,56.2 30.7,56.7 30.7,57.8 31.2,58.3 31.2,58.756 31.644,59.2 31.644,59.744 31.9,60 31.9,60.756 32.685,61.541 32.685,62.015 32.5,62.2 32.5,64 33.3,64.8 33.3,65.3 34.9,66.9 34.9,67.5 36.3,68.9 36.3,71.5 36.915,72.115 37.7,72.115 38.085,72.5 44.4,72.5 45.7,73.8 46.9,73.8 47.3,74.2 48.444,74.2 48.685,74.441 48.685,74.985 49.3,75.6 53.2,75.6 53.5,75.9 55.49,75.9 56.165,75.225 56.975,75.225 58.825,73.375 58.825,71.963 60.435,70.353 60.435,69.247 60,68.812 60,66.4 v1(59.4,65.8) ; v1(61.1,50.6) 61.7,50 61.7,48.8 61.45,48.55 61.45,46.25 61.6,46.1 61.6,42.7 62.5,41.8 62.5,39.1 62.1,38.7 62.1,38.1 62.4,37.8 62.4,36.116 64,34.516 64,32.7 64.315,32.385 64.315,30.465 65.5,29.28 J2.29@65.5,28.54
  L10 w0.114: v1(59.4,65.8) 59.4,65.544 57.7,63.844 57.7,53.4 60.5,50.6 v1(61.1,50.6)
GPIO_OR_PWM_2: R368.1 R369.1 U1.T25 | length 68.8
  L1 w0.114: v1(31.2,60.9) 31.6,60.5 31.6,59.5 32.4,58.7 U1.T25@32.4,58.1
  L1 w0.16: U1.T25@32.395,58.105 U1.T25@32.4,58.1
  L3 w0.12: v1(31.2,60.9) 31.266,60.9 31.885,61.519 31.885,62 32.1,62.215 32.1,64 32.515,64.415 32.515,65.215 34.5,67.2 34.5,67.7 35.985,69.185 35.985,72.085 37.5,73.6 39.644,73.6 40.129,73.115 44.115,73.115 45.2,74.2 46.756,74.2 48.456,75.9 52.9,75.9 53.2,76.2 55.756,76.2 56.441,75.515 57.21,75.515 59.2,73.525 59.2,72.1 60.725,70.575 60.725,69 60.4,68.675 60.4,66 v1(59.4,65)
  L10 w0.114: v1(59.4,65) 58.115,63.715 58.115,54.385 60,52.5 61.3,52.5 62,51.8 R368.1@62.1,51.8
GPIO_OR_PWM_3: J2.32 U1.B19 | length 89.8
  L1 w0.114: U1.B19@21.2,53.3 v1(21.6,53.7)
  L8 w0.12: v1(21.6,53.7) 22.8,52.5 22.8,50.356 22.529,50.085 22.241,50.085 22.015,49.859 22.015,49.6 21.985,49.57 21.985,49.541 21.759,49.315 21.315,49.315 21.185,49.185 21.185,45.029 19.3,43.144 19.3,41.844 18.915,41.459 18.915,40.929 20.8,39.044 20.8,36.2 21.185,35.815 21.185,34.075 22.615,32.645 22.615,32.341 22.856,32.1 24,32.1 24.2,32.3 28.3,32.3 28.985,31.615 28.985,30.115 30.125,28.975 30.125,27.681 31.4,26.406 31.4,24.1 34.756,20.744 35.1,20.744 36.815,19.029 36.815,18.541 37.156,18.2 37.6,18.2 37.9,18.5 41.4,18.5 42.7,17.2 46.9,17.2 47.2,16.9 47.2,16.656 48.521,15.335 50.065,15.335 50.815,14.585 59.685,14.585 62.615,17.515 62.615,18.509 62.9,18.794 62.9,18.8 63.1,19 63.1,20.4 64.8,22.1 66,22.1 66.8,22.9 66.8,24.76 J2.32@68.04,26
GPIO_OR_PWM_4: J2.33 U1.F17 | length 81.8
  L1 w0.114: v1(24,52.1) U1.F17@24.4,51.7
  L8 w0.12: v1(24,52.1) 23.5,51.6 23.5,50.6 22.815,49.915 22.815,49.571 22.559,49.315 22.155,49.315 21.985,49.145 21.985,44.741 19.615,42.371 19.615,41.541 20.1,41.056 20.1,40.256 21.2,39.156 21.2,36.4 21.6,36 21.6,34.1 22.785,32.915 23.9,32.915 24.085,33.1 28.3,33.1 29.3,32.1 29.3,30.3 30.415,29.185 30.415,28.559 31.8,27.174 31.8,24.8 32.1,24.5 32.4,24.5 33.2,23.7 33.2,23.1 34.94,21.36 35.2,21.36 37.56,19 41.5,19 42.885,17.615 47.429,17.615 48.1,16.944 48.1,16.3 48.665,15.735 50.759,15.735 51.494,15 58.5,15 59.5,16 60.3,16 61.8,17.5 61.8,18.5 62.7,19.4 62.7,20.5 65.5,23.3 J2.33@65.5,23.46
GYRO_CS_B: R317.2 U28.17 | length 1.7
  L1 w0.114: U28.17@41.2,30.225 41.2,29.2 R317.2@41.7,28.7
GYRO_INT: R313.2 R314.2 R410.1 U1.N24 | length 49
  L1 w0.114: U1.N24@30,57.3 30.291,57.3 30.691,56.9 v1(31.2,56.9) ; v1(37.4,36.9) 38,36.3 R410.1@38.5,36.3 R314.2@39.9,36.3 R313.2@41.3,36.3
  L8 w0.12: v1(31.2,56.9) 31.585,56.515 31.585,55.941 31.359,55.715 31.071,55.715 30.815,55.459 30.815,53.415 30.4,53 30.4,51.556 29.729,50.885 29.441,50.885 29.215,50.659 29.215,44.515 28.385,43.685 27.041,43.685 26.815,43.459 26.815,43.171 26.529,42.885 26.241,42.885 26.015,42.659 26.015,39.885 26.2,39.7 26.6,39.7 28.5,37.8 28.5,36.456 29.456,35.5 29.9,35.5 30.815,34.585 30.815,34.141 31.7,33.256 31.7,31.3 v1(32.1,30.9)
  L10 w0.114: v1(32.1,30.9) 32.485,30.515 33.215,30.515 34.1,31.4 34.1,35.244 ; 34.115,35.244 34.115,35.259 34.815,35.959 34.815,36.559 35.156,36.9 v1(37.4,36.9)
GYRO_INT1: R314.1 U28.3 | length 2.2
  L1 w0.114: R314.1@39.9,35.3 40,35.3 40.4,35.3 41.2,34.5 U28.3@41.2,33.975
GYRO_PWR_CTRL: R312.2 R313.1 U28.2 | length 2.9
  L1 w0.114: U28.2@41.7,33.975 41.7,34.5 41.3,34.9 R313.1@41.3,35.3 R312.2@42.7,35.3
GYRO_RST: R318.2 R383.2 U28.4 | length 24
  L1 w0.114: v1(40.7,33.1) U28.4@40.7,33.975
  L10 w0.114: v1(40.7,33.1) 40.7,33.4 41,33.7 42,33.7 42.3,33.4 R383.2@42.3,33.1 42.4,33 42.406,33 42.906,32.5 43.8,32.5 44.2,32.1 52.6,32.1 53.405,32.905 57.91,32.905 58.615,32.2 60.1,32.2 60.815,32.915 61.6,32.915 R318.2@61.6,33
HDMI_CEC: R25.1 U1.W4 | length 9.9
  L1 w0.114: U1.W4@34.8,41.3 35.2,40.9 35.8,40.9 36,40.7 36,38.7 36.535,38.165 36.535,37.709 36.7,37.544 36.7,33.9 36,33.2 R25.1@35.6,33.2
HDMI_CEC_CON: J5.13 R190.2 U12.23 | length 9
  L1 w0.114: J5.13@38,85.44 U12.23@38,82.05 38,80.756 40.7,78.056 R190.2@40.7,77.6
HDMI_CEC_IN: R24.2 R25.2 R118.1 U12.16 | length 63
  L1 w0.114: v1(24,35.7) 24.4,35.3 25.556,35.3 26,35.744 R24.2@26,35.9 26.9,36.8 28.5,36.8 29,36.3 30.344,36.3 30.729,35.915 31.159,35.915 31.429,36.185 32.015,36.185 34,34.2 34,33.8 R25.2@34.6,33.2 ; v1(38,75) U12.16@38,76.35
  L8 w0.12: v1(24,35.7) 24,40.24 23.615,40.625 23.615,42.659 24.671,43.715 24.959,43.715 26.015,44.771 26.015,48.515 26.9,49.4 26.9,51 27.615,51.715 27.615,53.059 27.871,53.315 28.26,53.315 29.215,54.27 29.215,54.659 29.215,55.459 29.441,55.685 29.729,55.685 30,55.956 30,58.2 30.5,58.7 30.5,60.8 31.1,61.4 31.1,61.9 31.62,62.42 31.62,63.731 32.185,64.296 32.185,66.685 33.135,67.635 33.135,68.421 32.815,68.741 32.815,69.059 33.015,69.259 33.015,70.259 34.2,71.444 34.2,73.5 35.1,74.4 37.4,74.4 v1(38,75)
  L10 w0.114: v1(38,75) 38.1,75.1 R118.1@38.6,75.1
HDMI_CLK_N: J5.12 U1.J5 U12.15 U12.24 | length 55.2
  L1 w0.1: v1(26.4,41.7) U1.J5@26.8,42.1 ; J5.12@37.5,85.44 37.5,84.09 37.16,83.75 37.16,83.47 37.5,83.13 U12.24@37.5,82.05 37.5,81.3 37.16,80.96 37.16,77.77 37.5,77.43 U12.15@37.5,76.35 37.5,75.6 37.16,75.26 37.16,74.983 37.783,74.36 38.893,74.36 39.46,73.793 39.46,73.24 v1(39.6,73.1)
  L8 w0.11: v1(26.4,41.7) 28.22,41.7 28.9,42.38 29.733,42.38 30.72,43.367 30.72,48.32 31.1,48.7 31.712,48.7 32.32,49.308 32.32,54.82 32.72,55.22 32.72,60.12 33.285,60.685 33.285,63.485 33.694,63.894 33.694,65.241 36.3,67.847 36.3,71.025 36.975,71.7 38.953,71.7 39.46,72.207 39.46,72.96 v1(39.6,73.1)
HDMI_CLK_P: J5.10 U1.J6 U12.13 U12.26 | length 55.2
  L1 w0.1: v1(26.4,42.5) U1.J6@26.8,42.9 ; J5.10@36.5,85.44 36.5,84.09 36.84,83.75 36.84,83.47 36.5,83.13 U12.26@36.5,82.05 36.5,81.3 36.84,80.96 36.84,77.77 36.5,77.43 U12.13@36.5,76.35 36.5,75.6 36.84,75.26 36.84,74.851 37.651,74.04 38.76,74.04 39.14,73.66 39.14,73.24 v1(39,73.1)
  L8 w0.11: v1(26.4,42.5) 26.4,42.393 26.773,42.02 28.088,42.02 28.768,42.7 29.6,42.7 30.4,43.5 30.4,43.9 30.075,44.225 30.075,44.675 30.4,45 30.4,48.453 30.967,49.02 31.58,49.02 32,49.44 32,54.953 32.4,55.353 32.4,60.253 32.965,60.818 32.965,63.618 33.374,64.026 33.374,65.374 35.98,67.98 35.98,71.158 36.842,72.02 38.82,72.02 39.14,72.34 39.14,72.96 v1(39,73.1)
HDMI_D0_N: J5.9 U1.K5 U12.12 U12.27 | length 57.5
  L1 w0.1: v1(27.2,42.5) U1.K5@27.6,42.1 ; J5.9@36,85.44 36,83.75 35.66,83.41 35.66,83.14 36,82.8 U12.27@36,82.05 36,80.97 35.66,80.63 35.66,77.77 36,77.43 U12.12@36,76.35 36,75.6 35.66,75.26 35.66,74.583 36.983,73.26 38.083,73.26 39.36,71.983 39.36,70.94 v1(39.5,70.8)
  L3 w0.11: v1(27.2,42.5) 27.72,41.98 28.5,41.98 28.9,42.38 29.733,42.38 30.8,43.447 30.8,47.153 30.52,47.433 30.52,48.367 31.033,48.88 31.908,48.88 32.42,49.392 32.42,50.38 32.1,50.7 32.1,55.447 32.8,56.147 32.8,57.847 33.9,58.947 33.9,60.847 34.5,61.447 34.5,62.947 35.24,63.687 35.24,64.64 35.58,64.98 36.133,64.98 36.7,65.547 36.7,66.4 38.68,68.38 40.233,68.38 40.82,68.967 40.82,69.733 40.353,70.2 39.5,70.2 39.36,70.34 39.36,70.66 v1(39.5,70.8)
HDMI_D0_P: J5.7 U1.K6 U12.10 U12.29 | length 57.5
  L1 w0.1: U1.K6@27.6,42.9 v1(28,42.5) ; J5.7@35,85.44 35,83.75 35.34,83.41 35.34,83.14 35,82.8 U12.29@35,82.05 35,80.97 35.34,80.63 35.34,77.77 35,77.43 U12.10@35,76.35 35,75.6 35.34,75.26 35.34,74.451 36.851,72.94 37.951,72.94 39.04,71.851 39.04,70.94 v1(38.9,70.8)
  L3 w0.11: v1(28,42.5) 28.2,42.3 28.368,42.3 28.768,42.7 29.6,42.7 30.48,43.58 30.48,44 30.34,44.14 30.097,44.14 29.937,44.3 29.937,44.6 30.097,44.76 30.34,44.76 30.48,44.9 30.48,45.65 30.34,45.79 30.097,45.79 29.937,45.95 29.937,46.25 30.087,46.4 30.33,46.4 30.48,46.55 30.48,47.02 30.2,47.3 30.2,48.5 30.9,49.2 31.775,49.2 32.1,49.525 32.1,50.247 31.78,50.567 31.78,55.58 32.48,56.28 32.48,57.98 33.58,59.08 33.58,60.98 34.18,61.58 34.18,63.08 34.92,63.82 34.92,64.773 35.447,65.3 36,65.3 36.38,65.68 36.38,66.533 38.547,68.7 40.1,68.7 40.5,69.1 40.5,69.6 40.22,69.88 39.367,69.88 39.04,70.207 39.04,70.66 v1(38.9,70.8)
HDMI_D1_N: J5.6 U1.J3 U12.9 U12.30 | length 55.2
  L1 w0.1: v1(26.4,40.1) U1.J3@26.8,40.5 ; J5.6@34.5,85.44 34.5,84.09 34.16,83.75 34.16,83.47 34.5,83.13 U12.30@34.5,82.05 34.5,81.3 34.16,80.96 34.16,77.44 34.5,77.1 U12.9@34.5,76.35 34.5,75.27 34.16,74.93 34.16,74.193 36.093,72.26 36.693,72.26 37.66,71.293 37.66,70.94 v1(37.8,70.8)
  L8 w0.11: v1(26.4,40.1) 28.981,40.1 31.301,42.42 32.124,42.42 33.919,44.215 33.919,59.167 34.6,59.847 34.6,63.147 35.24,63.787 35.24,64.787 37.66,67.207 37.66,70.66 v1(37.8,70.8)
HDMI_D1_P: J5.4 U1.J4 U12.7 U12.32 | length 55.2
  L1 w0.1: v1(26.4,40.9) U1.J4@26.8,41.3 ; J5.4@33.5,85.44 33.5,84.09 33.84,83.75 33.84,83.47 33.5,83.13 U12.32@33.5,82.05 33.5,81.3 33.84,80.96 33.84,77.44 33.5,77.1 U12.7@33.5,76.35 33.5,75.27 33.84,74.93 33.84,74.06 35.96,71.94 36.56,71.94 37.34,71.16 37.34,70.94 v1(37.2,70.8)
  L8 w0.11: v1(26.4,40.9) 26.4,40.793 26.773,40.42 28.848,40.42 29.128,40.7 29.128,41.153 29.375,41.4 29.828,41.4 31.168,42.74 31.992,42.74 33.599,44.348 33.599,59.299 34.28,59.98 34.28,63.28 34.92,63.92 34.92,64.92 37.34,67.34 37.34,70.66 v1(37.2,70.8)
HDMI_D2_N: J5.3 U1.K3 U12.6 U12.33 | length 57.5
  L1 w0.1: v1(27.2,40.9) U1.K3@27.6,40.5 ; J5.3@33,85.44 33,83.75 32.66,83.41 32.66,83.14 33,82.8 U12.33@33,82.05 33,80.97 32.66,80.63 32.66,77.77 33,77.43 U12.6@33,76.35 33,75.6 32.66,75.26 32.66,73.693 35.133,71.22 35.533,71.22 36.82,69.933 36.82,68.923 37.083,68.66 37.693,68.66 38.36,67.993 38.36,66.94 v1(38.5,66.8)
  L3 w0.11: v1(27.2,40.9) 27.43,40.67 27.43,40.317 27.867,39.88 28.761,39.88 31.301,42.42 32.124,42.42 33.7,43.996 33.7,44.747 34.2,45.247 34.2,46 33.62,46.58 33.62,47.967 34.145,48.492 34.145,49.355 33.599,49.901 33.599,54.9 34.02,55.321 34.02,57.267 35.1,58.347 35.1,60.3 35.658,60.858 35.658,61.706 37.8,63.847 37.8,65.547 38.36,66.107 38.36,66.66 v1(38.5,66.8)
HDMI_D2_P: J5.1 U1.K4 U12.4 U12.35 | length 57.5
  L1 w0.1: U1.K4@27.6,41.3 v1(28,40.9) ; J5.1@32,85.44 32,83.75 32.34,83.41 32.34,83.14 32,82.8 U12.35@32,82.05 32,80.97 32.34,80.63 32.34,77.77 32,77.43 U12.4@32,76.35 32,75.6 32.34,75.26 32.34,73.56 35,70.9 35.4,70.9 36.5,69.8 36.5,68.791 36.951,68.34 37.56,68.34 38.04,67.86 38.04,66.94 v1(37.9,66.8)
  L3 w0.11: v1(28,40.9) 27.9,40.9 27.75,40.75 27.75,40.45 28,40.2 28.628,40.2 29.128,40.7 29.128,40.928 28.939,41.118 28.939,41.301 29.155,41.518 29.339,41.518 29.528,41.328 29.757,41.328 31.168,42.74 31.992,42.74 32.38,43.128 32.38,43.505 32.595,43.72 32.972,43.72 33.38,44.128 33.38,44.88 33.88,45.38 33.88,45.867 33.3,46.447 33.3,48.1 33.825,48.625 33.825,49.223 33.279,49.768 33.279,55.033 33.7,55.453 33.7,57.4 34.78,58.48 34.78,60.433 35.338,60.991 35.338,61.838 37.48,63.98 37.48,65.68 38.04,66.24 38.04,66.66 v1(37.9,66.8)
HDMI_DDC: R24.1 R26.2 U1.K2 | length 8.6
  L1 w0.114: R24.1@25,35.9 24.6,36.3 R26.2@23.9,36.3 23.9,36.344 23.3,36.944 23.3,37.7 23.685,38.085 26.885,38.085 27.2,38.4 27.2,39.3 U1.K2@27.6,39.7
HDMI_ESD_BYP: C215.1 U12.37 | length 3.1
  L1 w0.28: 30.4,83.3 30.7,83.3 31,83 U12.37@31,82.05 U12.37@31,81.75
  L1 w0.4: C215.1@29.4,83 29.7,83.3 30.4,83.3
HDMI_HPD: R23.2 R357.2 U33.4 | length 5.6
  L10 w0.114: U33.4@36.95,79.95 36.95,79.25 36,78.3 R23.2@36,76.5 36.1,76.5 37.1,75.5 R357.2@37.3,75.5
HDMI_HPD_BUFF: R356.1 R357.1 U12.19 U33.2 | length 8
  L1 w0.114: v1(39.3,78.5) 39.985,77.815 39.985,76.835 U12.19@39.5,76.35
  L10 w0.114: R356.1@38.6,76.4 38.1,76.4 38,76.5 R357.1@37.3,76.5 37.3,77 37.6,77.3 U33.2@37.6,78.05 37.6,78.5 37.8,78.7 39.1,78.7 v1(39.3,78.5)
HDMI_HPD_CON: C217.1 J5.19 R47.2 U12.20 | length 4.5
  L1 w0.114: U12.20@39.6,81.7 R47.2@40.5,81.7 C217.1@40.5,83 41,83.5 J5.19@41,85.14
HDMI_HPD_R: C207.1 R21.1 R23.1 R157.2 U1.K1 | length 55
  L1 w0.114: v1(25.3,36.6) 25.8,36.6 26.3,37.1 C207.1@26.3,37.2 26.3,37.5 26.585,37.785 27.085,37.785 27.6,38.3 U1.K1@27.6,38.9
  L8 w0.12: v1(25.3,36.6) 25.3,38.544 24.944,38.9 24.656,38.9 24.415,39.141 24.415,42.659 24.641,42.885 24.929,42.885 25.215,43.171 25.215,43.459 26.271,44.515 26.559,44.515 26.785,44.741 26.785,45.255 27.2,45.67 27.2,48.8 27.5,49.1 27.5,50.544 27.856,50.9 28.4,50.9 28.7,51.2 28.7,53.344 29.471,54.115 29.759,54.115 30,54.356 30,55.436 30.3,55.736 30.3,57.3 30.8,57.8 30.8,60.244 31.041,60.485 31.329,60.485 31.9,61.056 31.9,63.615 32.465,64.18 32.465,66.465 33.585,67.585 33.585,69.455 33.815,69.685 33.815,70.315 34.6,71.1 34.6,72.3 35.8,73.5 36.9,73.5 37.4,73 v1(37.4,72.5)
  L10 w0.114: R23.1@36,75.5 36.1,75.5 37.4,74.2 R157.2@37.4,73.8 R21.1@38.6,73.8 38.6,73 38.1,72.5 v1(37.4,72.5)
HDMI_RESREF: R32.2 U1.J1 | length 2
  L1 w0.4: v1(26.4,38.5) U1.J1@26.8,38.9
  L10 w0.3: R32.2@25.865,37.3 25.865,37.9 26.4,38.435 v1(26.4,38.5)
HDMI_SCL_CON: J5.15 R183.1 | length 5.9
  L1 w0.114: v1(38.5,88) 39,87.5 J5.15@39,85.44
  L10 w0.114: R183.1@38.3,85.3 38.65,85.65 38.65,86.45 38.92,86.72 38.92,87.58 v1(38.5,88)
HDMI_SCL_CON_R: R183.2 R188.1 U12.22 | length 5
  L1 w0.114: v1(38.4,83.6) 38.5,83.5 U12.22@38.5,82.05
  L10 w0.114: R188.1@36.1,85.4 37.2,85.4 R183.2@37.3,85.3 37.3,84.7 v1(38.4,83.6)
HDMI_SDA_CON: J5.16 R184.1 | length 4.5
  L1 w0.114: v1(39.3,88) 39.5,87.8 J5.16@39.5,85.44
  L10 w0.114: v1(39.3,88) 39.3,86.9 39.5,86.7 R184.1@39.5,86.2
HDMI_SDA_CON_R: R184.2 R187.1 U12.21 | length 4.7
  L1 w0.114: U12.21@39,82.05 v1(39,83.1)
  L10 w0.114: v1(39,83.1) 39,84.7 R184.2@39.5,85.2 R187.1@40.8,85.2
